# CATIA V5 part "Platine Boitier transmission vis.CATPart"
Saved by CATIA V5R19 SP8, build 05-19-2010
Part number: Corps sup BMV
Nomenclature: 70_b
Bounding box of the stored display mesh (mm): x -32.5 to 85.5, y -32.5 to 32.5, z 0 to 40.09
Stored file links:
  C:\Users\rphgr\Desktop\0_Tapis_TC520B_vitesse\Platine Boitier transmission vis.CATPart
  C:\Users\rphgr\Desktop\0_Tapis_TC520B_vitesse\CE_Boitier_Moteur_Vis.CATProduct
  C:\Users\rphgr\Desktop\0_Tapis_TC520B_vitesse\Corps Inf de BMV.CATPart
  D:\Documents\1_Travail\1 - ac-limoges.fr\ac-limoges.fr\Emmanuel Maynard - STI2D_Turgot\3 - Supports\Tapis de course TC520B\Tapis de course TC520B_Ca\Roue_11.CATPart
  D:\Programmes\DassaultSysteme\win_b64\reffiles\standard\MetricThickPitch.txt
  D:\Documents\1_Travail\1 - ac-limoges.fr\ac-limoges.fr\Emmanuel Maynard - STI2D_Turgot\3 - Supports\Tapis de course TC520B\Tapis de course TC520B_Ca\Bloc moteur_vis\Roue_2-3.CATPart
  D:\Documents\1_Travail\1 - ac-limoges.fr\ac-limoges.fr\Emmanuel Maynard - STI2D_Turgot\3 - Supports\Tapis de course TC520B\Tapis de course TC520B_Ca\Bloc moteur_vis\Roue_5-6.CATPart
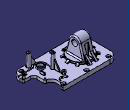
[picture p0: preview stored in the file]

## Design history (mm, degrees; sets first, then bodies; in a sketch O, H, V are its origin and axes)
Set1
  DatumSurface1 to DatumSurface3: linked copy from another document
  DatumCurve1 to DatumCurve5: linked copy from another document
Body1 (main body)
  AxisSystem1: origin (0, 0, 0), X (1, 0, 0), Y (0, 1, 0), Z (0, 0, 1)
  Sketch1 on XY plane of AxisSystem1, origin (0, 0, 0), H (1, 0, 0), V (0, 1, 0)
    projected arc E1 centre (-19.5, 19.5) radius 13 from (-19.5, 32.5) to (-32.5, 19.5) ccw from edge of DatumSurface1
    point P1 (-19.5, 32.5)
    projected line E2 (-32.5, -19.5) -> (-32.5, 19.5) from edge of DatumSurface1
    projected arc E3 centre (-19.5, -19.5) radius 13 from (-32.5, -19.5) to (-19.5, -32.5) ccw from edge of DatumSurface1
    projected line E4 (72.5, -32.5) -> (-19.5, -32.5) from edge of DatumSurface1
    projected arc E5 centre (72.5, -19.5) radius 13 from (72.5, -32.5) to (85.5, -19.5) ccw from edge of DatumSurface1
    point P10 (85.5, -19.5)
    projected line E6 (85.5, 19.5) -> (85.5, -19.5) from edge of DatumSurface1
    projected line E7 (85.5, -15.5) -> (85.5, -19.5) from edge of DatumSurface1
    point P12 (85.5, -19.5)
    projected line E8 (-19.5, 32.5) -> (72.5, 32.5) from edge of DatumSurface1
    projected line E9 (-19.5, 32.5) -> (61, 32.5) from edge of DatumSurface1
    point P13 (-19.5, 32.5)
    projected arc E10 centre (20.5, -28.5) radius 3.621 from (23.3554, -26.2732) to (17.4815, -30.5) ccw from edge of DatumSurface1
    projected arc E11 centre (20.5, -28.5) radius 3.621 from (23.5185, -30.5) to (17.4815, -30.5) ccw from edge of DatumSurface1
    point P16 (17.4815, -30.5)
    projected line E12 (-19.5, -30.5) -> (17.4815, -30.5) from edge of DatumSurface1
    point P18 (17.4815, -30.5)
    projected arc E13 centre (-19.5, -19.5) radius 11 from (-22.3711, -30.1187) to (-19.5, -30.5) ccw from edge of DatumSurface1
    projected arc E14 centre (-22.5, -26.5) radius 3.621 from (-22.3711, -30.1187) to (-22.5919, -22.8802) ccw from edge of DatumSurface1
    projected arc E15 centre (-26.5, -22.0279) radius 4 from (-22.5919, -22.8802) to (-30.386, -21.0797) ccw from edge of DatumSurface1
    projected arc E16 centre (-19.5, -19.5) radius 11 from (-30.5, -19.5) to (-30.386, -21.0797) ccw from edge of DatumSurface1
    projected line E17 (-30.5, 19.5) -> (-30.5, -19.5) from edge of DatumSurface1
    projected arc E18 centre (-19.5, 19.5) radius 11 from (-25.2093, 28.9023) to (-30.5, 19.5) ccw from edge of DatumSurface1
    projected arc E19 centre (-22.5, 26.5) radius 3.621 from (-25.2093, 28.9023) to (-22.3711, 30.1187) ccw from edge of DatumSurface1
    projected arc E20 centre (-19.5, 19.5) radius 11 from (-19.5, 30.5) to (-22.3711, 30.1187) ccw from edge of DatumSurface1
    projected line E21 (14.4815, 30.5) -> (-19.5, 30.5) from edge of DatumSurface1
    projected arc E22 centre (17.5, 28.5) radius 3.621 from (14.4815, 30.5) to (20.5185, 30.5) ccw from edge of DatumSurface1
    projected line E23 (48.0359, 30.5) -> (20.5185, 30.5) from edge of DatumSurface1
    projected arc E24 centre (51.5, 28.5) radius 4 from (48.0359, 30.5) to (50.5868, 24.6056) ccw from edge of DatumSurface1
    projected line E25 (71.3542, -18.9643) -> (50.5868, 24.6056) from edge of DatumSurface1
    projected line E26 (51.7414, 24.5073) -> (72.2569, -18.534) from edge of DatumSurface1
    projected arc E27 centre (51.5, 28.5) radius 4 from (51.7414, 24.5073) to (54.7407, 26.1552) ccw from edge of DatumSurface1
    projected arc E28 centre (51.5, 28.5) radius 4 from (50.5868, 24.6056) to (54.7407, 26.1552) ccw from edge of DatumSurface1
    point P48 (54.7407, 26.1552)
    projected arc E29 centre (57.5, 28.5) radius 3.621 from (54.7407, 26.1552) to (60.5185, 30.5) ccw from edge of DatumSurface1
    projected arc E30 centre (57.5, 28.5) radius 3.621 from (54.7407, 26.1552) to (56.507, 25.0178) ccw from edge of DatumSurface1
    projected arc E31 centre (57.5, 28.5) radius 3.621 from (59.882, 25.7727) to (61, 29.4282) ccw from edge of DatumSurface1
    point P49 (54.7407, 26.1552)
    projected line E32 (72.5, 30.5) -> (60.5185, 30.5) from edge of DatumSurface1
    projected line E33 (83.5, -19.5) -> (83.5, 19.5) from edge of DatumSurface1
    projected line E34 (83.5, -19.5) -> (83.5, -15.5) from edge of DatumSurface1
    point P53 (83.5, -19.5)
    projected arc E35 centre (72.5, -19.5) radius 11 from (78.2093, -28.9023) to (83.5, -19.5) ccw from edge of DatumSurface1
    point P56 (83.5, -19.5)
    projected arc E36 centre (75.5, -26.5) radius 3.621 from (78.2093, -28.9023) to (74.4083, -23.0475) ccw from edge of DatumSurface1
    projected line E37 (73.5056, -23.4778) -> (74.4083, -23.0475) from edge of DatumSurface1
    projected arc E38 centre (75.5, -26.5) radius 3.621 from (73.5056, -23.4778) to (75.3711, -30.1187) ccw from edge of DatumSurface1
    projected arc E39 centre (72.5, -19.5) radius 11 from (72.5, -30.5) to (75.3711, -30.1187) ccw from edge of DatumSurface1
    point P63 (72.5, -30.5)
    projected line E40 (23.5185, -30.5) -> (72.5, -30.5) from edge of DatumSurface1
    projected line E41 (23.5185, -30.5) -> (72.5, -30.5) from edge of DatumSurface1
    point P66 (72.5, -30.5)
    projected arc E42 centre (20.5, -28.5) radius 3.621 from (23.5185, -30.5) to (24.0735, -29.0846) ccw from edge of DatumSurface1
    projected circle E43 centre (-22.5, -26.5) radius 1.621 from edge of DatumSurface1
    projected circle E44 centre (-26.5, -22.0279) radius 2 from edge of DatumSurface1
    projected circle E45 centre (75.5, -26.5) radius 1.621 from edge of DatumSurface1
    projected circle E46 centre (20.5, -28.5) radius 1.621 from edge of DatumSurface1
    projected circle E47 centre (17.5, 28.5) radius 1.621 from edge of DatumSurface1
    projected circle E48 centre (57.5, 28.5) radius 1.621 from edge of DatumSurface1
    projected circle E49 centre (-22.5, 26.5) radius 1.621 from edge of DatumSurface1
    projected circle E50 centre (51.5, 28.5) radius 2 from edge of DatumSurface1
    arc A1 centre (67.395, 17.1706) radius 11.4211 from (59.882, 25.7727) to (64.6247, 6.0906) ccw
    point P69 (67.395, 17.1706)
    line L1 (61, 32.5) -> (61, 29.4282)
    line L2 (67.2, 2.7921) -> (67.2, -8.5)
    line L3 (72.2, -13.5) -> (83.5, -13.5)
    reference intersected line E51 (-32.5, -19.5) -> (-32.5, 19.5) from face of DatumSurface2
    reference intersected line E52 (-32.5, -19.5) -> (-32.5, 19.5) from face of DatumSurface2
    reference intersected line E53 (71.5, -32.5) -> (-20.5, -32.5) from face of DatumSurface3
    arc A2 centre (72.2, -8.5) radius 5 from (67.2, -8.5) to (72.2, -13.5) ccw
    reference projected point E54 (67.395, 17.1706) from edge of DatumCurve2
    point P73 (61, 32.5)
    point P74 (85.5, -13.5)
    point P75 (61, 29.4282)
    point P76 (61, 29.4282)
    point P77 (59.882, 25.7727)
    point P78 (85.5, -13.5)
    arc A3 centre (67.395, 17.1706) radius 13.4211 from (56.507, 25.0178) to (65.2, 3.9302) ccw
    line L4 (65.2, 3.9302) -> (65.2, -8.5)
    arc A4 centre (72.2, -8.5) radius 7 from (65.2, -8.5) to (72.2, -15.5) ccw
    line L5 (72.2, -15.5) -> (83.5, -15.5)
    point P81 (83.5, -15.5)
    point P82 (83.5, -15.5)
    point P83 (56.507, 25.0178)
    point P84 (56.507, 25.0178)
    arc A5 centre (83.5, -15.5) radius 2 from (83.5, -13.5) to (85.5, -15.5) cw
    arc A6 centre (63.8, 2.7921) radius 3.4 from (64.6247, 6.0906) to (67.2, 2.7921) cw
    distance L1 E51 = 93.5
    distance L2 E52 = 99.7
    distance E53 L3 = 19
    radius A2 = 5
    distance L3 L5 = 2
    distance L4 L2 = 2
    distance A3 A1 = 2
    distance A4 A2 = 2
    radius A5 = 2
    radius A6 = 3.4
    tangency: A2 L2, A2 L3, A1 E29, A4 L4, A4 L5, A5 L3, A5 E6, A6 A1, A6 L2
    coincidence: P69 E54, E8 P73, L3 P74, L1 P75, E29 P76, E29 P77, E6 P78, L5 P81, E33 P82, A3 P83, E29 P84, L3 P78, E6 P74, P1 P13, P10 P12, P16 P18, P49 P48, P53 P56, P66 P63, P75 P76, P81 P82, P83 P84
    concentricity: A3 A1
  Pad1: profile Sketch1, direction (0, 0, 1), length 7.1
  Sketch2 on end face of Pad1, origin (0, 0, 7.1), H (1, 0, 0), V (0, 1, 0)
    projected arc E1 centre (-19.5, -19.5) radius 11 from (-22.3711, -30.1187) to (-19.5, -30.5) ccw from edge [end face of Pad1 | face of Pad1 from Sketch1.E13]
    projected arc E2 centre (-22.5, -26.5) radius 3.621 from (-22.3711, -30.1187) to (-22.5919, -22.8802) ccw from edge [end face of Pad1 | face of Pad1 from Sketch1.E14]
    projected arc E3 centre (-26.5, -22.0279) radius 4 from (-22.5919, -22.8802) to (-30.386, -21.0797) ccw from edge [end face of Pad1 | face of Pad1 from Sketch1.E15]
    projected arc E4 centre (-19.5, -19.5) radius 11 from (-30.5, -19.5) to (-30.386, -21.0797) ccw from edge [end face of Pad1 | face of Pad1 from Sketch1.E16]
    projected line E5 (-30.5, 19.5) -> (-30.5, -19.5) from edge [end face of Pad1 | face of Pad1 from Sketch1.E17]
    projected arc E6 centre (-19.5, 19.5) radius 11 from (-25.2093, 28.9023) to (-30.5, 19.5) ccw from edge [end face of Pad1 | face of Pad1 from Sketch1.E18]
    projected arc E7 centre (-22.5, 26.5) radius 3.621 from (-25.2093, 28.9023) to (-22.3711, 30.1187) ccw from edge [end face of Pad1 | face of Pad1 from Sketch1.E19]
    projected arc E8 centre (-19.5, 19.5) radius 11 from (-19.5, 30.5) to (-22.3711, 30.1187) ccw from edge [end face of Pad1 | face of Pad1 from Sketch1.E20]
    projected line E9 (14.4815, 30.5) -> (-19.5, 30.5) from edge [end face of Pad1 | face of Pad1 from Sketch1.E21]
    projected arc E10 centre (17.5, 28.5) radius 3.621 from (14.4815, 30.5) to (20.5185, 30.5) ccw from edge [end face of Pad1 | face of Pad1 from Sketch1.E22]
    projected line E11 (48.0359, 30.5) -> (20.5185, 30.5) from edge [end face of Pad1 | face of Pad1 from Sketch1.E23]
    projected arc E12 centre (51.5, 28.5) radius 4 from (48.0359, 30.5) to (50.5868, 24.6056) ccw from edge [end face of Pad1 | face of Pad1 from Sketch1.E24]
    projected arc E13 centre (51.5, 28.5) radius 4 from (50.5868, 24.6056) to (54.7407, 26.1552) ccw from edge [end face of Pad1 | face of Pad1 from Sketch1.E28]
    projected arc E14 centre (57.5, 28.5) radius 3.621 from (54.7407, 26.1552) to (56.507, 25.0178) ccw from edge [end face of Pad1 | face of Pad1 from Sketch1.E31]
    projected arc E15 centre (67.395, 17.1706) radius 13.4211 from (56.507, 25.0178) to (65.2, 3.9302) ccw from edge [end face of Pad1 | face of Pad1 from Sketch1.A3]
    projected line E16 (65.2, -8.5) -> (65.2, 3.9302) from edge [end face of Pad1 | face of Pad1 from Sketch1.L4]
    projected arc E17 centre (72.2, -8.5) radius 7 from (65.2, -8.5) to (72.2, -15.5) ccw from edge [end face of Pad1 | face of Pad1 from Sketch1.A4]
    projected line E18 (83.5, -15.5) -> (72.2, -15.5) from edge [end face of Pad1 | face of Pad1 from Sketch1.L5]
    projected line E19 (83.5, -19.5) -> (83.5, -15.5) from edge [end face of Pad1 | face of Pad1 from Sketch1.E34]
    projected arc E20 centre (72.5, -19.5) radius 11 from (78.2093, -28.9023) to (83.5, -19.5) ccw from edge [end face of Pad1 | face of Pad1 from Sketch1.E35]
    projected arc E21 centre (75.5, -26.5) radius 3.621 from (78.2093, -28.9023) to (74.4083, -23.0475) ccw from edge [end face of Pad1 | face of Pad1 from Sketch1.E36]
    projected line E22 (73.5056, -23.4778) -> (74.4083, -23.0475) from edge [end face of Pad1 | face of Pad1 from Sketch1.E37]
    projected arc E23 centre (75.5, -26.5) radius 3.621 from (73.5056, -23.4778) to (75.3711, -30.1187) ccw from edge [end face of Pad1 | face of Pad1 from Sketch1.E38]
    projected arc E24 centre (72.5, -19.5) radius 11 from (72.5, -30.5) to (75.3711, -30.1187) ccw from edge [end face of Pad1 | face of Pad1 from Sketch1.E39]
    projected line E25 (23.5185, -30.5) -> (72.5, -30.5) from edge [end face of Pad1 | face of Pad1 from Sketch1.E41]
    projected arc E26 centre (20.5, -28.5) radius 3.621 from (23.5185, -30.5) to (17.4815, -30.5) ccw from edge [end face of Pad1 | face of Pad1 from Sketch1.E11]
    projected line E27 (-19.5, -30.5) -> (17.4815, -30.5) from edge [end face of Pad1 | face of Pad1 from Sketch1.E12]
    projected circle E28 centre (51.5, 28.5) radius 2 from edge [end face of Pad1 | face of Pad1 from Sketch1.E50]
    projected circle E29 centre (-26.5, -22.0279) radius 2 from edge [end face of Pad1 | face of Pad1 from Sketch1.E44]
  Pad2: profile Sketch2, direction (0, 0, -1), length 3.3
  Sketch3 on face of Pad2, origin (0, 0, 7.1), H (1, 0, 0), V (0, 1, 0)
    circle A1 centre (-22.5, 26.5) radius 3.5
    circle A2 centre (17.5, 28.5) radius 3.5
    point P2 (17.5, 28.5)
    circle A3 centre (57.5, 28.5) radius 3.5
    point P3 (57.5, 28.5)
    circle A4 centre (75.5, -26.5) radius 3.5
    point P4 (75.5, -26.5)
    circle A5 centre (20.5, -28.5) radius 3.5
    point P5 (20.5, -28.5)
    circle A6 centre (-22.5, -26.5) radius 3.5
    point P6 (-22.5, -26.5)
    reference projected point E1 (-22.5, 26.5) from axis of face of Pad1 from Sketch1.E49
    reference projected point E2 (17.5, 28.5) from axis of face of Pad1 from Sketch1.E47
    reference projected point E3 (57.5, 28.5) from axis of face of Pad1 from Sketch1.E48
    reference projected point E4 (75.5, -26.5) from axis of face of Pad1 from Sketch1.E45
    reference projected point E5 (20.5, -28.5) from axis of face of Pad1 from Sketch1.E46
    reference projected point E6 (-22.5, -26.5) from axis of face of Pad1 from Sketch1.E43
    radius A1 = 3.5
    radius A2 = 3.5
    radius A3 = 3.5
    radius A4 = 3.5
    radius A5 = 3.5
    radius A6 = 3.5
    concentricity: A1 E1
    coincidence: P2 E2, P3 E3, P4 E4, P5 E5, P6 E6
  Pocket1: profile Sketch3, direction (0, 0, -1), length 3.15
  Sketch4 on YZ plane of AxisSystem1, origin (0, 0, 0), H (0, 1, 0), V (0, 0, 1)
    arc A1 centre (0, 30.1) radius 10 from (9.6124, 32.857) to (-9.6124, 32.857) ccw
    point P1 (0, 30.1)
    line L1 (-9.6124, 32.857) -> (-17, 7.1)
    point P3 (-17, 7.1)
    line L2 (-17, 7.1) -> (17, 7.1)
    point P4 (17, 7.1)
    line L3 (17, 7.1) -> (9.6124, 32.857)
    reference intersected line E1 through (0, 7.1) direction (-1, 0) from face of Pad2
    circle A2 centre (0, 30.1) radius 5
    reference intersected line E2 through (0, 7.1) direction (-1, 0) from face of Pad2
    distance P4 V = 17 {= Sketch4.distance(P4 P3) /2}
    distance P4 P3 = 34
    radius A2 = 5
    distance A2 A1 = 5
    distance P1 E2 = 23
    coincidence: P1 V, L2 E1
    tangency: L1 A1, L3 A1
    horizontal: L2 H
  Pad3: profile Sketch4, direction (1, 0, 0), length 10, mirrored extent
  Sketch5 on YZ plane of AxisSystem1, origin (0, 0, 0), H (0, 1, 0), V (0, 0, 1)
    line L1 (14.1318, 17.1) -> (24.1318, 7.1)
    point P1 (14.1318, 17.1)
    point P2 (24.1318, 7.1)
    reference intersected line E1 through (0, 7.1) direction (-1, 0) from face of Pad2
    reference intersected line E2 (9.6124, 32.857) -> (17, 7.1) from face of Pad3 from Sketch4.L3
    reference intersected line E3 through (0, 7.1) direction (-1, 0) from face of Pad2
    reference intersected line E4 through (0, 7.1) direction (-1, 0) from face of Pad2
    angle L1 E3 = 45
    distance P1 E4 = 10
    coincidence: P2 E1, P1 E2
  Stiffener1: ThicknessValue 14, ExtendedProfile Sketch5, ThicknessTop 0
  Mirror1: of Stiffener1, about ZX plane of AxisSystem1
  Sketch6 on face of Pad2, origin (0, 0, 7.1), H (1, 0, 0), V (0, 1, 0)
    point P1 (0, -17.3159)
    line L1 (3, -10.5) -> (3, -24.1318)
    line L2 (3, -24.1318) -> (-3, -24.1318)
    line L3 (-3, -24.1318) -> (-3, -10.5)
    line L4 (-3, -10.5) -> (3, -10.5)
    point P6 (0, 17.3159)
    line L5 (3, 24.1318) -> (3, 10.5)
    line L6 (3, 10.5) -> (-3, 10.5)
    line L7 (-3, 10.5) -> (-3, 24.1318)
    line L8 (-3, 24.1318) -> (3, 24.1318)
    point P9 (-3, 10.5)
    reference intersected line E1 through (0, 0) direction (-1, 0) from ZX plane of AxisSystem1
    reference projected line E2 (-7, 24.1318) -> (7, 24.1318) from edge [face of Stiffener1 from Sketch5.L1 | face of Pad2]
    reference projected line E3 (7, -24.1318) -> (-7, -24.1318) from edge [face of Mirror1 | face of Pad2]
    distance L1 L3 = 6
    distance L4 L6 = 21
    coincidence: P1 V, P6 V, P9 L3, L8 E2, L2 E3
    vertical: L1 V, L3 V, L5 V, L7 V
    horizontal: L2 H, L4 H, L6 H, L8 H
    equidistance: L1 L3 P1, L2 L4 P1, L5 L7 P6, L6 L8 P6
    symmetry: L4 L6 E1
  Pocket2: profile Sketch6, direction (0, 0, 1), through (limit type 3)
  Sketch7 on face of Pocket2, origin (0, 0, 7.1), H (1, 0, 0), V (0, 1, 0)
    circle A1 centre (0, 0) radius 20
    radius A1 = 20
  Pad4: profile Sketch7, direction (0, 0, 1), length 3
  Sketch8 on ZX plane of AxisSystem1, origin (0, 0, 0), H (0, 0, 1), V (1, 0, 0)
    line L1 (9.6, -20) -> (7.1, -24.5)
    point P1 (9.6, -20)
    point P2 (7.1, -24.5)
    reference intersected line E1 through (7.1, 0) direction (0, 1) from face of Pad2
    reference projected line E2 through (0, 0) direction (1, 0) from axis of face of Pad4 from Sketch7.A1
    reference intersected line E3 (10.1, -20) -> (10.1, 20) from end face of Pad4
    distance P2 P1 V = 4.5
    distance P1 E2 = 20
    distance P1 E3 = 0.5
    coincidence: P2 E1
  Stiffener2: ThicknessValue 4, ExtendedProfile Sketch8, ThicknessTop 0
  CircPattern1: of Stiffener2, instances 10, angular step 36 {= 360.0*1 deg/CircPattern1.AngularNumber}, axis from face of Pad4 from Sketch7.A1
  Fillet1: radius 0.4, on edge [face of Pad4 from Sketch7.A1 | end face of Pad4] (x4)
  Fillet2: radius 0.4, on face of Stiffener1 (x2); face of Pocket2 from Sketch6.L5; face of Pocket2 from Sketch6.L7; face of Mirror1 (x2); face of Pocket2 from Sketch6.L3; face of Pocket2 from Sketch6.L1; edge [face of Pad3 from Sketch4.L1 | face of Mirror1] (x2); edge [face of Pad3 from Sketch4.L3 | face of Stiffener1 from Sketch5.L1] (x2)
  Fillet3: radius 0.4, on 1 edge
  Fillet4: radius 0.4, on edge [face of Stiffener2 | face of Stiffener2] (x2); edge [face of CircPattern1 | face of CircPattern1] (x14)
  Fillet5: radius 0.4, on edge [face of Pocket2 | face of Pad4 from Sketch7.A1] (x6); edge [face of Pocket2 | face of Pad4] (x4); edge [end face of Pad4 | face of Pocket2 from Sketch6.L6]; edge [end face of Pad4 | face of Pocket2 from Sketch6.L4]
  Fillet6: radius 2, on edge [start face of Pad3 | face of Pad3 from Sketch4.L3]; edge [start face of Pad3 | end face of Pad4]; edge [end face of Pad4 | face of Pad3 from Sketch4.L3] (x2); edge [face of Pad3 from Sketch4.L1 | end face of Pad4] (x2); edge [face of Pad3 from Sketch4.A1 | end face of Pad3]; edge [end face of Pad4 | end face of Pad3]
  Sketch9 on face of Pocket2, origin (0, 0, 7.1), H (1, 0, 0), V (0, 1, 0)
    circle A1 centre (51.2639, -17.5) radius 5
    reference projected point E1 (51.2639, -17.5) from edge of DatumCurve3
    radius A1 = 5
    concentricity: A1 E1
  Pocket3: profile Sketch9, direction (0, 0, -1), through (limit type 3)
  Sketch10 on face of Pocket2, origin (0, 0, 7.1), H (1, 0, 0), V (0, 1, 0)
    arc A1 centre (51.2639, -17.5) radius 9 from (42.2639, -17.5) to (58.7472, -22.5) ccw
    line L1 (42.2639, -17.5) -> (42.2639, 20)
    arc A2 centre (44.7639, 20) radius 2.5 from (42.2639, 20) to (47.2639, 20) cw
    line L2 (47.2639, 20) -> (47.2639, 19)
    arc A3 centre (50.7639, 19) radius 3.5 from (47.2639, 19) to (54.2639, 19) ccw
    point P7 (50.7639, 19)
    line L3 (54.2639, 19) -> (54.2639, 20.5)
    arc A4 centre (56.2639, 20.5) radius 2 from (54.2639, 20.5) to (56.2639, 22.5) cw
    line L4 (56.2639, 22.5) -> (83.4571, 22.5)
    line L5 (58.7472, -22.5) -> (95.4719, -22.5)
    reference intersected line E1 (71.5, -32.5) -> (-20.5, -32.5) from face of Pad1 from Sketch1.E4
    reference projected point E2 (51.2639, -17.5) from axis of face of Pocket3 from Sketch9.A1
    reference intersected line E3 (-20.5, 32.5) -> (60, 32.5) from face of Pad1 from Sketch1.E9
    reference projected line E4 (60, 32.5) -> (-20.5, 32.5) from edge [start face of Pad1 | face of Pad1 from Sketch1.E9]
    line L6 (83.4571, 22.5) -> (95.4719, -22.5)
    distance L5 E1 = 10
    radius A1 = 9
    radius A2 = 2.5
    radius A3 = 3.5
    distance L4 E3 = 10
    distance P7 E4 = 13.5
    radius A4 = 2
    tangency: L1 A1, A2 L1, L2 A2, A3 L2, L3 A3, A4 L3, L4 A4, L4 A2
    horizontal: L5 H, L4 H
    concentricity: A1 E2
    vertical: L1 V, L2 V, L3 V
  Pocket4: profile Sketch10, direction (0, 0, -1), length 2
  Sketch11 on end face of Pocket4, origin (0, 0, 5.1), H (1, 0, 0), V (0, 1, 0)
    circle A1 centre (51.2639, -17.5) radius 6
    projected circle E1 centre (51.2639, -17.5) radius 5 from edge [end face of Pocket4 | face of Pocket3 from Sketch9.A1]
    reference projected point E2 (51.2639, -17.5) from axis of face of Pocket3 from Sketch9.A1
    distance A1 E1 = 1
    concentricity: A1 E2
  Pad5: profile Sketch11, direction (0, 0, 1), length 2.8
  Sketch12 on face of Pocket2, origin (50.5093, 19, 7.1), H (1, 0, 0), V (0, 1, 0)
    point P1 (0.2546, 0)
    reference projected point E1 (0.2546, 0) from axis of face of Pocket4 from Sketch10.A3
    coincidence: P1 E1
  Hole1: placed by Sketch12, at (50.7639, 19, 7.1) direction (0, 0, -1), diameter 3.242, through (limit type 3), threaded "M4", thread diameter 4, thread depth 3.3, pitch 0.7
  Fillet7: radius 2, on edge [face of Pocket4 from Sketch10.L4 | face of Pad1 from Sketch1.A1]
  Sketch13 on end face of Pad2, origin (0, 0, 3.8), H (1, 0, 0), V (0, -1, 0)
    circle A1 centre (63.8, -2.7921) radius 3.4
    reference projected arc E1 centre (63.8, -2.7921) radius 3.4 from (64.8081, -6.0392) to (67.2, -2.7921) ccw from edge [start face of Pad1 | face of Pad1 from Sketch1.A6]
    coincidence: A1 E1
  Pad6: profile Sketch13, direction (0, 0, -1), up to start face of Pad1
  Fillet8: radius 1, on edge [face of Pad6 from Sketch13.A1 | face of Pad1 from Sketch1.L4]; edge [face of Pad1 from Sketch1.A3 | face of Pad6 from Sketch13.A1]
  Sketch14 on end face of Pocket4, origin (63.3747, 3.2768, 5.1), H (1, 0, 0), V (0, 1, 0)
    point P1 (0.4253, -0.4846)
    reference projected point E1 (0.4253, -0.4846) from axis of face of Pad1 from Sketch1.A6
    coincidence: P1 E1
  Hole2: placed by Sketch14, at (63.8, 2.7921, 5.1) direction (0, 0, -1), diameter 2.459, through (limit type 3), threaded "M3", thread diameter 3, thread depth 5.1, pitch 0.5
  Sketch15 on end face of Pocket4, origin (72.1035, -19.1971, 5.1), H (1, 0, 0), V (0, 1, 0)
    point P1 (2.3965, -0.3172)
    reference projected point E1 (-8.3035, 21.9892) from axis of face of Hole2
    reference intersected line E2 (13.3965, 2.6971) -> (13.3965, -0.3029) from face of Pad1 from Sketch1.E7
    distance P1 E1 = 24.74
    distance P1 E2 = 11
  Hole3: placed by Sketch15, at (74.5, -19.5143, 5.1) direction (0, 0, -1), diameter 2.459, through (limit type 3), threaded "M3", thread diameter 3, thread depth 1.3, pitch 0.5
  Sketch16 on end face of Pocket4, origin (0, 0, 5.1), H (1, 0, 0), V (0, 1, 0)
    circle A1 centre (41.3, -5.9) radius 3.6
    point P1 (41.3, -5.9)
    circle A2 centre (62.015, -27.6) radius 3.6
    point P2 (62.015, -27.6)
    reference intersected line E1 (71.5, -32.5) -> (-20.5, -32.5) from face of Pad1 from Sketch1.E4
    reference intersected line E2 (-20.5, 32.5) -> (60, 32.5) from face of Pad1 from Sketch1.E9
    reference intersected line E3 (67.2, 2.3705) -> (67.2, -9.5) from face of Pad1 from Sketch1.L2
    radius A2 = 3.6
    radius A1 = 3.6
    distance P2 E1 = 4.9
    distance P1 E2 = 38.4
    distance P1 E3 = 25.9
    distance P2 P1 = 30
  Pad7: profile Sketch16, direction (0, 0, 1), length 23
  Draft1: PullDir face of Pocket2, Angle 2, SupportToDraft (face of Pad7 from Sketch16.A2; face of Pad7 from Sketch16.A1), Neutral end face of Pocket4
  Sketch17 on end face of Pad7, origin (40.2109, -5.9, 28.1), H (1, 0, 0), V (0, 1, 0)
    point P1 (1.0891, 0)
    reference projected point E1 (1.0891, 0) from edge
    coincidence: P1 E1
  Hole4: placed by Sketch17, at (41.3, -5.9, 28.1) direction (0, 0, -1), diameter 2.459, depth 18, V-bottom angle 120, threaded "M3", thread diameter 3, thread depth 15, pitch 0.5
  Sketch18 on end face of Pad7, origin (60.5901, -27.6, 28.1), H (1, 0, 0), V (0, 1, 0)
    point P1 (1.4249, 0)
    reference projected point E1 (1.4249, 0) from edge
    coincidence: E1 P1
  Hole5: placed by Sketch18, at (62.015, -27.6, 28.1) direction (0, 0, -1), diameter 2.459, depth 18, V-bottom angle 120, threaded "M3", thread diameter 3, thread depth 15, pitch 0.5
  Plane1: type OffsetPt, RefPlane YZ plane of AxisSystem1, RefPoint {point type Center, Curve edge [end face of Pad7 | face of Hole4]}
  Sketch19 on Plane1, origin (41.3, 0, 0), H (0, 1, 0), V (0, 0, 1)
    line L1 (-3.3174, 20.1) -> (5.6, 7.1)
    point P1 (-3.3174, 20.1)
    point P2 (5.6, 7.1)
    reference intersected line E1 through (0, 7.1) direction (-1, 0) from face of Pocket2
    reference projected point E2 (-5.9, 108.1905) from edge
    reference intersected line E3 through (0, 7.1) direction (-1, 0) from face of Pocket2
    distance E1 P1 = 13
    distance P2 E2 H = 11.5
    coincidence: P2 E3
  Stiffener3: ThicknessValue 2, ExtendedProfile Sketch19, ThicknessTop 0
  Plane2: type OffsetPt, RefPlane ZX plane of AxisSystem1, RefPoint {point type Center, Curve edge [face of Pad7 from Sketch16.A2 | end face of Pad7]}
  Sketch20 on Plane2, origin (0, -27.6, 0), H (-1, 0, 0), V (0, 0, 1)
    line L1 (-58.0992, 20.1) -> (-50.015, 7.1)
    point P1 (-58.0992, 20.1)
    point P2 (-50.015, 7.1)
    reference intersected line E1 through (0, 7.1) direction (-1, 0) from face of Pocket2
    reference intersected line E2 through (0, 7.1) direction (-1, 0) from face of Pocket2
    reference projected point E3 (-62.015, 108.1905) from edge
    distance P1 E1 = 13
    distance P2 E3 H = 12
    coincidence: P2 E2
  Stiffener4: ThicknessValue 2, ExtendedProfile Sketch20, ThicknessTop 0
  Fillet9: radius 0.2, on edge [face of Pad7 from Sketch16.A1 | end face of Pad7]; edge [face of Pad7 from Sketch16.A2 | end face of Pad7]; face of Stiffener4 (x2); edge [face of Pad7 from Sketch16.A2 | face of Pocket2]; edge [face of Pad7 from Sketch16.A1 | face of Pocket2]; face of Stiffener3 (x2); edge [face of Pad7 from Sketch16.A1 | end face of Pocket4]; edge [face of Pad7 from Sketch16.A1 | face of Pocket4 from Sketch10.L1]
  Sketch21 on end face of Pocket4, origin (0, 0, 5.1), H (1, 0, 0), V (0, -1, 0)
    circle A1 centre (40.5, -12.3) radius 2.85
    point P1 (40.5, -12.3)
    reference intersected line E1 (60, -32.5) -> (-20.5, -32.5) from face of Pad1 from Sketch1.E9
    reference intersected line E2 (-32.5, -19.5) -> (-32.5, 19.5) from face of Pad1 from Sketch1.E2
    circle A2 centre (81.4778, 16.35) radius 2.5
    point P2 (81.4778, 16.35)
    radius A1 = 2.85
    distance P1 E1 = 20.2
    distance P1 E2 = 73
    radius A2 = 2.5
    distance P2 P1 = 50
  Pad8: profile Sketch21, direction (0, 0, 1), length 4.6
  Sketch22 on end face of Pad8, origin (39.5, 12.3, 9.7), H (1, 0, 0), V (0, 1, 0)
    point P1 (1, 0)
    reference projected point E1 (1, 0) from axis of face of Pad8 from Sketch21.A1
    coincidence: P1 E1
  Hole6: placed by Sketch22, at (40.5, 12.3, 9.7) direction (0, 0, -1), diameter 2.459, through (limit type 3), threaded "M3", thread diameter 3, thread depth 5.9, pitch 0.5
  Sketch23 on end face of Pad8, origin (79.6211, -16.8809, 9.7), H (1, 0, 0), V (0, 1, 0)
    point P1 (1.8567, 0.5309)
    reference projected point E1 (1.8567, 0.5309) from axis of face of Pad8 from Sketch21.A2
    coincidence: P1 E1
  Hole7: placed by Sketch23, at (81.4778, -16.35, 9.7) direction (0, 0, -1), diameter 2.459, through (limit type 3), threaded "M3", thread diameter 3, thread depth 5.9, pitch 0.5
  Fillet10: radius 0.2, on edge [end face of Pad8 | face of Pad8 from Sketch21.A2]; edge [face of Pad8 from Sketch21.A2 | end face of Pocket4]; edge [end face of Pad8 | face of Pad8 from Sketch21.A1]; edge [face of Pocket2 | face of Pad8 from Sketch21.A1]
  Sketch24 on end face of Pocket4, origin (0, 0, 5.1), H (1, 0, 0), V (0, 1, 0)
    line L1 (58.56, -1.8) -> (60.56, -1.8)
    line L2 (60.56, -1.8) -> (60.56, -9.8)
    line L3 (60.56, -9.8) -> (58.56, -9.8)
    line L4 (58.56, -9.8) -> (58.56, -1.8)
    reference intersected line E1 (67.2, 2.3705) -> (67.2, -9.5) from face of Pad1 from Sketch1.L2
    reference intersected line E2 (95.4719, -22.5) -> (58.7173, -22.5) from face of Pocket4 from Sketch10.L5
    distance L4 L2 = 2
    distance L1 L3 = 8
    distance L4 E1 = 8.64
    distance L1 E2 = 20.7
    horizontal: L1 H, L3 H
    vertical: L2 V, L4 V
  Pad9: profile Sketch24, direction (0, 0, 1), length 3.7, opposite side up to end face of Pocket4
  Draft2: PullDir end face of Pad9, Angle 2, SupportToDraft (face of Pad9 from Sketch24.L1; face of Pad9 from Sketch24.L2; face of Pad9 from Sketch24.L3; face of Pad9 from Sketch24.L4), Neutral end face of Pocket4
  Fillet11: radius 0.2, on edge [face of Pad9 from Sketch24.L2 | face of Pad9 from Sketch24.L1]; edge [face of Pad9 from Sketch24.L3 | face of Pad9 from Sketch24.L2]; edge [face of Pad9 from Sketch24.L4 | face of Pad9 from Sketch24.L3]; edge [face of Pad9 from Sketch24.L4 | face of Pad9 from Sketch24.L1]
  Fillet12: radius 0.2, on edge [face of Pad9 from Sketch24.L1 | end face of Pad9]; edge [face of Pad9 from Sketch24.L2 | end face of Pad9]; edge [face of Pad9 from Sketch24.L3 | end face of Pad9]; edge [face of Pad9 from Sketch24.L4 | end face of Pad9]
  Fillet13: radius 0.2, on edge [face of Pad9 from Sketch24.L1 | end face of Pocket4]; edge [face of Pad9 from Sketch24.L2 | end face of Pocket4]; edge [face of Pad9 from Sketch24.L3 | end face of Pocket4]; edge [face of Pad9 from Sketch24.L4 | end face of Pocket4]
  Fillet14: radius 0.2, on edge [face of Pocket4 from Sketch10.L5 | face of Pocket4 from Sketch10.A1]
  Sketch25 on end face of Pad2, origin (0, 0, 3.8), H (1, 0, 0), V (0, -1, 0)
    circle A1 centre (74.5, 19.5143) radius 3.5
    point P1 (74.5, 19.5143)
    reference projected point E1 (74.5, 19.5143) from axis of face of Hole3
    projected circle E2 centre (74.5, 19.5143) radius 1.2295 from edge [face of Hole3 | end face of Pad2]
    radius A1 = 3.5
    coincidence: P1 E1
  Pad10: profile Sketch25, direction (0, 0, -1), up to face of Pad1
  Fillet15: radius 1.5, on edge [face of Pad1 from Sketch1.E16 | face of Pad1 from Sketch1.E15]; edge [face of Pad1 from Sketch1.E15 | face of Pad1 from Sketch1.E14]; edge [face of Pad1 from Sketch1.E14 | face of Pad1 from Sketch1.E13]; edge [face of Pad1 from Sketch1.E12 | face of Pad1 from Sketch1.E11]; edge [face of Pad1 from Sketch1.E11 | face of Pad1 from Sketch1.E41]; edge [face of Pad1 from Sketch1.E39 | face of Pad1 from Sketch1.E38]; edge [face of Pad1 from Sketch1.E36 | face of Pad1 from Sketch1.E35]; edge [face of Pad1 from Sketch1.A3 | face of Pad1 from Sketch1.E31]; edge [face of Pad1 from Sketch1.E31 | face of Pad1 from Sketch1.E28]; edge [face of Pad1 from Sketch1.E24 | face of Pad1 from Sketch1.E23]; edge [face of Pad1 from Sketch1.E22 | face of Pad1 from Sketch1.E21]; edge [face of Pad1 from Sketch1.E23 | face of Pad1 from Sketch1.E22]; edge [face of Pad1 from Sketch1.E20 | face of Pad1 from Sketch1.E19]; edge [face of Pad1 from Sketch1.E19 | face of Pad1 from Sketch1.E18]; edge [face of Pad1 from Sketch1.E36 | face of Pad10 from Sketch25.A1]
  Sketch26 on end face of Pad2, origin (0, 0, 3.8), H (1, 0, 0), V (0, -1, 0)
    circle A1 centre (0, 0) radius 13.1
    radius A1 = 13.1
  Pocket5: profile Sketch26, direction (0, 0, 1), length 3
  Fillet16: radius 0.2, on face of Pocket5 from Sketch26.A1
  Sketch27 on end face of Pocket5, origin (0, 0, 6.8), H (1, 0, 0), V (0, -1, 0)
    circle A1 centre (0, 0) radius 8
    radius A1 = 8
  Pocket6: profile Sketch27, direction (0, 0, 1), length 13
  Sketch28 on end face of Pad2, origin (0, 0, 3.8), H (1, 0, 0), V (0, -1, 0)
    line L1 (45.734, -24.6056) -> (50.5868, -24.6056)
    arc A1 centre (45.734, -20.0367) radius 4.5689 from (41.1651, -20.0367) to (45.734, -24.6056) ccw
    line L2 (41.1651, -20.0367) -> (41.1651, -14.428)
    arc A2 centre (51.2639, 17.5) radius 10.0988 from (58.4379, 24.6077) to (41.1651, 17.5) ccw
    line L3 (58.4379, 24.6077) -> (72.087, 25.2905)
    reference projected point E1 (51.2639, 17.5) from axis of face of Pad5
    projected arc E2 centre (51.5, -28.5) radius 4 from (50.5868, -24.6056) to (47.5166, -28.8636) ccw from edge [end face of Pad2 | face of Pad1 from Sketch1.E24]
    point P5 (50.5868, -24.6056)
    projected arc E3 centre (46.0228, -29) radius 1.5 from (46.0228, -30.5) to (47.5166, -28.8636) ccw from edge [face of Fillet15 | end face of Pad2]
    projected line E4 (25.5965, 30.5) -> (71.0307, 30.5) from edge [end face of Pad2 | face of Pad1 from Sketch1.E41]
    projected line E5 (25.1651, 30.5) -> (71.0307, 30.5) from edge [end face of Pad2 | face of Pad1 from Sketch1.E41]
    point P10 (71.0307, 30.5)
    projected arc E6 centre (71.0307, 29) radius 1.5 from (72.3398, 28.2677) to (71.0307, 30.5) ccw from edge [face of Fillet15 | end face of Pad2]
    point P11 (72.3398, 28.2677)
    point P12 (71.0307, 30.5)
    point P14 (50.5868, -24.6056)
    line L4 (25.1651, 30.5) -> (25.1651, -30.5)
    point P15 (25.1651, 30.5)
    line L5 (25.1651, -30.5) -> (46.0228, -30.5)
    projected arc E7 centre (75.5, 26.5) radius 3.621 from (72.3398, 28.2677) to (73.5056, 23.4778) ccw from edge [face of Pad1 from Sketch1.E38 | face of Pad1]
    projected arc E8 centre (75.5, 26.5) radius 3.621 from (72.3398, 28.2677) to (72.087, 25.2905) ccw from edge [face of Pad1 from Sketch1.E38 | face of Pad1]
    point P17 (72.3398, 28.2677)
    arc A3 centre (40.5, -12.3) radius 2.2295 from (41.1651, -14.428) to (41.1651, -10.172) ccw
    reference projected point E9 (40.5, -12.3) from axis of face of Hole6
    reference projected circle E10 centre (40.5, -12.3) radius 1.2295 from edge [face of Hole6 | end face of Pad2]
    point P20 (41.1651, -10.172)
    line L6 (41.1651, -10.172) -> (41.1651, 17.5)
    distance L4 L2 = 16
    radius A1 = 4.5689
    distance E10 A3 = 1
    concentricity: A2 E1, A3 E9
    coincidence: P15 E4, P14 P5, P10 P12, P11 P17, L2 P20, L2 L6
    perpendicularity: L4 L1
    tangency: L2 A1, A1 L1, A2 L2, L5 E3
    horizontal: L1 H
  Pocket7: profile Sketch28, direction (0, 0, 1), length 2
  Fillet17: radius 0.2, on face of Pocket7 from Sketch28.L4; face of Pocket7 from Sketch28.L2; face of Pocket7 from Sketch28.A3; face of Pocket7 from Sketch28.L6; face of Pocket7 from Sketch28.L3
  Sketch29 on end face of Pocket7, origin (0, 0, 5.8), H (1, 0, 0), V (0, -1, 0)
    circle A1 centre (32.3478, -8.7104) radius 4
    point P1 (32.3478, -8.7104)
    circle A2 centre (32.3478, -8.7104) radius 2.8
    reference projected point E1 (32.3478, -8.7104) from edge of DatumCurve4
    radius A2 = 2.8
    radius A1 = 4
    coincidence: P1 E1
  Pad11: profile Sketch29, direction (0, 0, -1), up to face of Pad1, offset -2
  Sketch30 on end face of Pocket7, origin (0, 0, 5.8), H (1, 0, 0), V (0, -1, 0)
    circle A1 centre (36.5339, 16.2872) radius 2.5
    point P1 (36.5339, 16.2872)
    circle A2 centre (36.5339, 16.2872) radius 1.25
    reference projected point E1 (36.5339, 16.2872) from edge of DatumCurve5
    radius A2 = 1.25
    radius A1 = 2.5
    coincidence: P1 E1
  Pad12: profile Sketch30, direction (0, 0, -1), length 2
